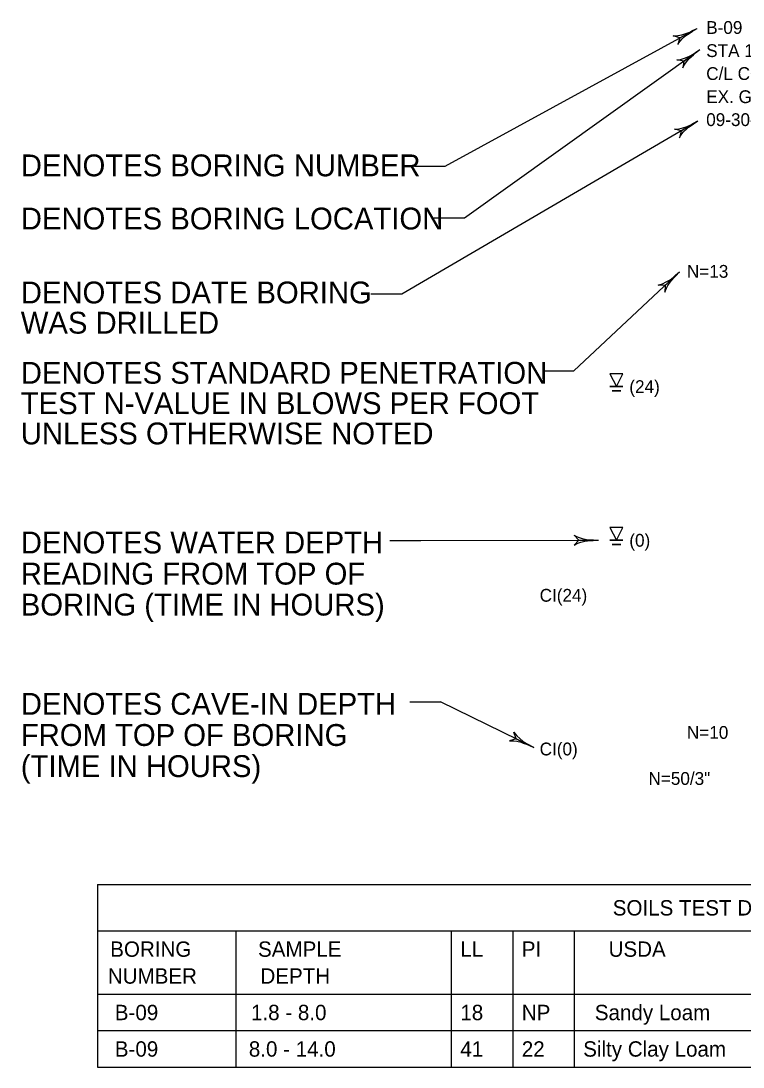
# Model space of a CAD drawing. Extents: x 1.3 to 42.5, y -2.5 to 22.6.
# Drawn here: x 19.47 to 23.44, y 5.49 to 11.24 of the extents above; entities that cross this region are included whole.
import ezdxf

# ---------------------------------------------------------------- set-up
doc = ezdxf.new("R2010")
doc.units = 0
doc.layers.add('B-SOIL-BORE', color=7, linetype='Continuous')

msp = doc.modelspace()

# ---------------------------------------------------------------- linework, layer by layer
at = {"layer": 'B-SOIL-BORE'}
for p, q in [((21.8009, 10.4403), (23.1832, 11.1966)), ((23.0885, 11.1451), (23.0521, 11.1559)), ((23.0521, 11.1559), (23.0629, 11.1555)), ((23.0629, 11.1555), (23.0775, 11.1571)), ((23.0775, 11.1571), (23.0995, 11.1617)), ((23.0885, 11.1451), (23.1833, 11.1969)), ((23.0995, 11.1617), (23.1223, 11.1679)), ((23.1021, 11.1401), (23.1195, 11.1559)), ((23.1195, 11.1559), (23.1309, 11.1633)), ((23.1223, 11.1679), (23.1435, 11.1765)), ((23.1309, 11.1633), (23.1455, 11.1731)), ((23.1435, 11.1765), (23.1579, 11.1845)), ((23.1455, 11.1731), (23.1579, 11.1815)), ((23.1579, 11.1845), (23.1833, 11.1969)), ((23.1579, 11.1815), (23.1833, 11.1969)), ((23.1833, 11.1969), (23.1833, 11.1969)), ((23.0885, 11.1451), (23.0779, 11.1083)), ((23.0779, 11.1083), (23.0837, 11.1175)), ((23.0837, 11.1175), (23.0917, 11.1283)), ((23.0917, 11.1283), (23.1021, 11.1401)), ((21.9072, 10.1561), (23.1984, 11.0799)), ((23.0979, 11.0281), (23.1195, 11.0351)), ((23.1107, 11.0173), (23.1987, 11.0799)), ((23.1195, 11.0351), (23.1415, 11.0441)), ((23.1247, 11.0137), (23.1403, 11.0317)), ((23.1403, 11.0317), (23.1503, 11.0405)), ((23.1415, 11.0441), (23.1617, 11.0551)), ((23.1503, 11.0405), (23.1639, 11.0519)), ((23.1617, 11.0551), (23.1747, 11.0645)), ((23.1639, 11.0519), (23.1751, 11.0615)), ((23.1747, 11.0645), (23.1987, 11.0799)), ((23.1751, 11.0615), (23.1987, 11.0799)), ((23.1987, 11.0799), (23.1987, 11.0799)), ((23.0731, 11.0235), (23.0839, 11.0245)), ((23.1107, 11.0173), (23.0731, 11.0235)), ((23.0839, 11.0245), (23.0979, 11.0281)), ((23.1107, 11.0173), (23.1045, 10.9795)), ((23.1045, 10.9795), (23.1091, 10.9895)), ((23.1091, 10.9895), (23.1157, 11.0009)), ((23.1157, 11.0009), (23.1247, 11.0137)), ((21.563, 9.7381), (23.1883, 10.689)), ((23.0961, 10.6333), (23.1885, 10.6893)), ((23.1635, 10.6757), (23.1885, 10.6893)), ((23.1635, 10.6727), (23.1885, 10.6893)), ((23.1885, 10.6893), (23.1885, 10.6893)), ((23.0589, 10.6425), (23.0699, 10.6429)), ((23.0961, 10.6333), (23.0589, 10.6425)), ((23.0699, 10.6429), (23.0841, 10.6453)), ((23.0841, 10.6453), (23.1061, 10.6507)), ((23.0961, 10.6333), (23.0869, 10.5963)), ((23.0995, 10.6169), (23.1095, 10.6291)), ((23.1061, 10.6507), (23.1285, 10.6579)), ((23.1095, 10.6291), (23.1265, 10.6455)), ((23.1265, 10.6455), (23.1373, 10.6537)), ((23.1285, 10.6579), (23.1495, 10.6673)), ((23.1373, 10.6537), (23.1517, 10.6639)), ((23.1495, 10.6673), (23.1635, 10.6757)), ((23.1517, 10.6639), (23.1635, 10.6727)), ((23.0869, 10.5963), (23.0921, 10.6059)), ((23.0921, 10.6059), (23.0995, 10.6169)), ((21.6322, 10.4403), (21.8009, 10.4403)), ((21.7385, 10.1561), (21.9072, 10.1561)), ((23.0868, 9.8592), (22.5078, 9.3161)), ((23.0083, 9.7855), (23.0869, 9.8593)), ((23.0351, 9.8161), (23.0537, 9.8299)), ((23.0445, 9.8139), (23.0563, 9.8269)), ((23.0537, 9.8299), (23.0653, 9.8409)), ((23.0563, 9.8269), (23.0663, 9.8379)), ((23.0653, 9.8409), (23.0869, 9.8593)), ((23.0663, 9.8379), (23.0869, 9.8593)), ((23.0869, 9.8593), (23.0869, 9.8593)), ((22.9699, 9.7867), (22.9807, 9.7893)), ((23.0083, 9.7855), (22.9699, 9.7867)), ((22.9807, 9.7893), (22.9943, 9.7945)), ((22.9943, 9.7945), (23.0145, 9.8045)), ((23.0083, 9.7855), (23.0069, 9.7473)), ((23.0103, 9.7577), (23.0153, 9.7699)), ((23.0145, 9.8045), (23.0351, 9.8161)), ((23.0153, 9.7699), (23.0227, 9.7839)), ((23.0227, 9.7839), (23.0355, 9.8037)), ((23.0355, 9.8037), (23.0445, 9.8139)), ((21.3942, 9.7381), (21.563, 9.7381)), ((23.0069, 9.7473), (23.0103, 9.7577)), ((22.3391, 9.3161), (22.5078, 9.3161)), ((22.5355, 8.3865), (22.5085, 8.4135)), ((22.5085, 8.4135), (22.5179, 8.4081)), ((22.5179, 8.4081), (22.5315, 8.4027)), ((22.5315, 8.4027), (22.5531, 8.3959)), ((22.5531, 8.3959), (22.5761, 8.3905)), ((22.5761, 8.3905), (22.5989, 8.3881)), ((22.5989, 8.3881), (22.6151, 8.3881)), ((22.6151, 8.3881), (22.6435, 8.3867)), ((21.4982, 8.3844), (21.6669, 8.3844)), ((21.6669, 8.3844), (22.6435, 8.3865)), ((22.5355, 8.3865), (22.5089, 8.3595)), ((22.5089, 8.3595), (22.5183, 8.3649)), ((22.5183, 8.3649), (22.5301, 8.3703)), ((22.5301, 8.3703), (22.5449, 8.3757)), ((22.5355, 8.3865), (22.6435, 8.3867)), ((22.5449, 8.3757), (22.5679, 8.3811)), ((22.5679, 8.3811), (22.5815, 8.3823)), ((22.5815, 8.3823), (22.5989, 8.3839)), ((22.5989, 8.3839), (22.6139, 8.3853)), ((22.6139, 8.3853), (22.6435, 8.3867)), ((22.6435, 8.3867), (22.6435, 8.3867)), ((21.6069, 7.4983), (21.7757, 7.4983)), ((22.2876, 7.2482), (21.7757, 7.4983)), ((22.1907, 7.2959), (22.1783, 7.3317)), ((22.1783, 7.3317), (22.1845, 7.3229)), ((22.1845, 7.3229), (22.1943, 7.3121)), ((22.1943, 7.3121), (22.2107, 7.2967)), ((22.2107, 7.2967), (22.2289, 7.2815)), ((22.1907, 7.2959), (22.1545, 7.2835)), ((22.1545, 7.2835), (22.1653, 7.2841)), ((22.1653, 7.2841), (22.1789, 7.2837)), ((22.1789, 7.2837), (22.1945, 7.2819)), ((22.1907, 7.2959), (22.2877, 7.2483)), ((22.1945, 7.2819), (22.2175, 7.2767)), ((22.2175, 7.2767), (22.2301, 7.2721)), ((22.2289, 7.2815), (22.2483, 7.2691)), ((22.2301, 7.2721), (22.2467, 7.2657)), ((22.2467, 7.2657), (22.2605, 7.2603)), ((22.2483, 7.2691), (22.2629, 7.2621)), ((22.2605, 7.2603), (22.2877, 7.2483)), ((22.2629, 7.2621), (22.2877, 7.2483)), ((22.2877, 7.2483), (22.2877, 7.2483)), ((19.8937, 6.4947), (26.8125, 6.4947)), ((19.8937, 6.4947), (19.8937, 6.2416)), ((19.8937, 6.2416), (26.8125, 6.2416)), ((19.8937, 6.2416), (19.8937, 6.0412)), ((20.6531, 6.2416), (20.6531, 6.0412)), ((21.8343, 6.2416), (21.8343, 6.0412)), ((22.1718, 6.2416), (22.1718, 6.0412)), ((22.5093, 6.2416), (22.5093, 6.0412)), ((19.8937, 6.0939), (19.8937, 5.8935)), ((20.6531, 6.0939), (20.6531, 5.8935)), ((21.8343, 6.0939), (21.8343, 5.8935)), ((22.1718, 6.0939), (22.1718, 5.8935)), ((22.5093, 6.0939), (22.5093, 5.8935)), ((19.8937, 5.8935), (26.8125, 5.8935)), ((19.8937, 5.8935), (19.8937, 5.6931)), ((20.6531, 5.8935), (20.6531, 5.6931)), ((21.8343, 5.8935), (21.8343, 5.6931)), ((22.1718, 5.8935), (22.1718, 5.6931)), ((22.5093, 5.8935), (22.5093, 5.6931)), ((19.8937, 5.6931), (26.8125, 5.6931)), ((19.8937, 5.6931), (19.8937, 5.4927)), ((20.6531, 5.6931), (20.6531, 5.4927)), ((21.8343, 5.6931), (21.8343, 5.4927)), ((22.1718, 5.6931), (22.1718, 5.4927)), ((22.5093, 5.6931), (22.5093, 5.4927)), ((19.8937, 5.4927), (26.8125, 5.4927))]:
    msp.add_line(p, q, dxfattribs=at)
for points in [[(22.7408, 9.2297), (22.776, 9.3001), (22.7057, 9.3001)], [(22.7057, 9.2297), (22.7057, 9.2297), (22.776, 9.2297)], [(22.7174, 9.2063), (22.7174, 9.2063), (22.7643, 9.2063)], [(22.7408, 8.386), (22.776, 8.4563), (22.7057, 8.4563)], [(22.7057, 8.386), (22.7057, 8.386), (22.776, 8.386)], [(22.7174, 8.3626), (22.7174, 8.3626), (22.7643, 8.3626)]]:
    msp.add_lwpolyline(points, close=True, dxfattribs=at)

# ---------------------------------------------------------------- texts
for s, height, p in [('B-09', 0.07031, (23.2337, 11.1663)), ('STA 123+45,20 RT', 0.070308, (23.2337, 11.0393)), ('C/L CONST. MD 650', 0.070308, (23.2337, 10.9133)), ('EX. GRD. ELEV.  125+/-', 0.070308, (23.2337, 10.7863)), ('09-30-2002', 0.07031, (23.2337, 10.6603)), ('DENOTES BORING NUMBER', 0.12, (19.4727, 10.3843)), ('DENOTES BORING LOCATION', 0.12, (19.4727, 10.0923)), ('N=13', 0.07031, (23.1277, 9.8273)), ('DENOTES DATE BORING', 0.12, (19.4727, 9.6863)), ('WAS DRILLED', 0.12, (19.4727, 9.5203)), ('DENOTES STANDARD PENETRATION', 0.12, (19.4727, 9.2453)), ('(24)', 0.07031, (22.8117, 9.1943)), ('TEST N-VALUE IN BLOWS PER FOOT', 0.12, (19.4727, 9.0783)), ('UNLESS OTHERWISE NOTED', 0.12, (19.4727, 8.9123)), ('DENOTES WATER DEPTH ', 0.12, (19.4727, 8.3133)), ('(0)', 0.07031, (22.8117, 8.3503)), ('READING FROM TOP OF', 0.12, (19.4727, 8.1423)), ('CI(24)', 0.07031, (22.3197, 8.0483)), ('BORING (TIME IN HOURS) ', 0.12, (19.4727, 7.9723)), ('DENOTES CAVE-IN DEPTH', 0.12, (19.4727, 7.4273)), ('FROM TOP OF BORING', 0.12, (19.4727, 7.2563)), ('N=10', 0.07031, (23.1277, 7.2953)), ('CI(0)', 0.07031, (22.3197, 7.2043)), ('(TIME IN HOURS)', 0.12, (19.4727, 7.0853)), ('N=50/3"', 0.07031, (22.9167, 7.0423)), ('SOILS TEST DATA', 0.08437, (22.7208, 6.3251)), (' BORING', 0.08437, (19.932, 6.0983)), ('SAMPLE', 0.08437, (20.7744, 6.0983)), (' LL', 0.08437, (21.8532, 6.0983)), (' PI', 0.08437, (22.1904, 6.0983)), ('USDA', 0.08437, (22.698, 6.0983)), (' NUMBER ', 0.08437, (19.9188, 5.9507)), ('DEPTH', 0.08437, (20.7876, 5.9507)), (' B-09', 0.08437, (19.9572, 5.7503)), ('1.8 - 8.0', 0.08437, (20.736, 5.7503)), (' 18', 0.08437, (21.8532, 5.7503)), (' NP', 0.08437, (22.1904, 5.7503)), ('Sandy Loam', 0.08437, (22.6224, 5.7503)), (' B-09', 0.08437, (19.9572, 5.5499)), ('8.0 - 14.0', 0.08437, (20.724, 5.5499)), (' 41', 0.08437, (21.8532, 5.5499)), (' 22', 0.08437, (22.1904, 5.5499)), ('Silty Clay Loam', 0.08437, (22.5588, 5.5499))]:
    msp.add_text(s, height=height, dxfattribs=at).set_placement(p)

doc.saveas('drawing.dxf')
